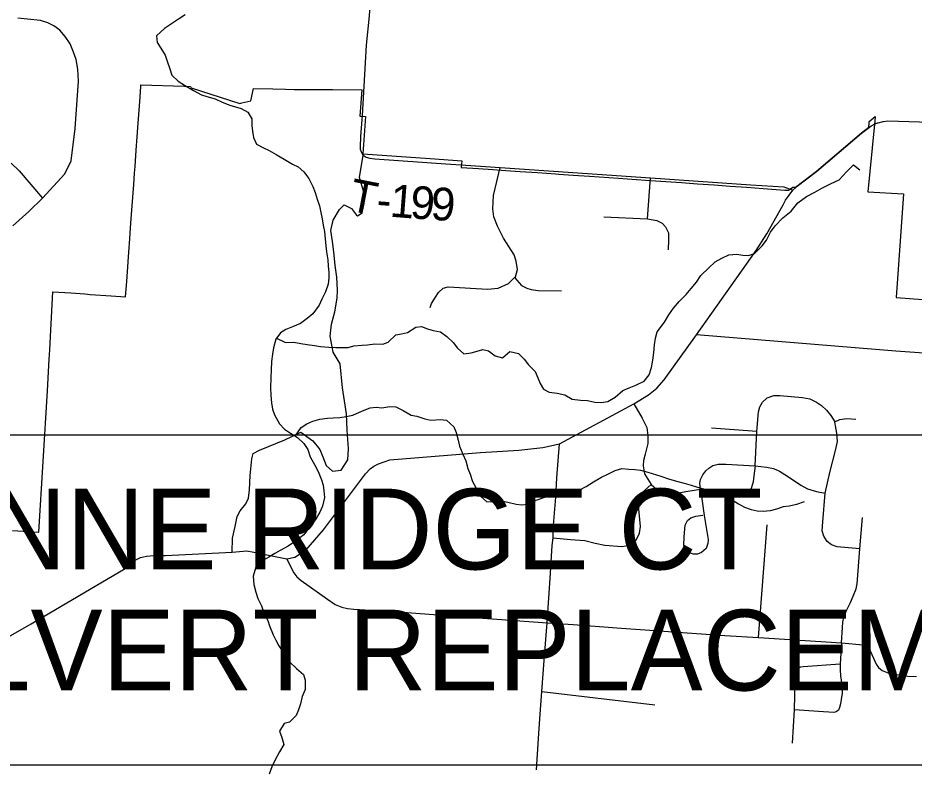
# Model space of a CAD drawing. Extents: x 208586767.6 to 208586821.4, y -134301046.9 to -134301022.9.
# Drawn here: x 208586781.515 to 208586783.069, y -134301028.957 to -134301027.656 of the extents above; entities that cross this region are included whole.
import ezdxf

# ---------------------------------------------------------------- set-up
doc = ezdxf.new("R2010")
doc.units = 0
for name, color, linetype in [('GM_X_City_Street', 7, 'Continuous'), ('GM_X_Corporation', 7, 'Continuous'), ('GM_X_County_Road', 7, 'Continuous'), ('GM_X_Minor_River', 7, 'Continuous'), ('GM_X_Township_Road', 7, 'Continuous'), ('GM_X_Township_Road_Text', 7, 'Continuous'), ('SH_Text', 7, 'Continuous')]:
    doc.layers.add(name, color=color, linetype=linetype)

msp = doc.modelspace()

# ---------------------------------------------------------------- linework, layer by layer
at = {"layer": 'GM_X_City_Street'}
for points in [[(208586781.5061, -134301028.0164), (208586781.534, -134301027.9913), (208586781.5576, -134301027.9684), (208586781.5965, -134301027.9262), (208586781.6071, -134301027.9038), (208586781.6143, -134301027.8478), (208586781.6198, -134301027.7655), (208586781.6188, -134301027.7446), (208586781.6157, -134301027.7277), (208586781.6115, -134301027.715), (208586781.6053, -134301027.7004), (208586781.5969, -134301027.6877), (208586781.5879, -134301027.6772), (208586781.5775, -134301027.6694), (208586781.5667, -134301027.6642), (208586781.5542, -134301027.66), (208586781.5313, -134301027.658), (208586781.5147, -134301027.6561)], [(208586781.5032, -134301027.9077), (208586781.5174, -134301027.9208), (208586781.5576, -134301027.9684)]]:
    msp.add_lwpolyline(points, dxfattribs=at)
at = {"layer": 'GM_X_Corporation'}
msp.add_lwpolyline([(208586781.5056, -134301028.5447), (208586781.5515, -134301028.5481), (208586781.5663, -134301028.3027), (208586781.5692, -134301028.2476), (208586781.5701, -134301028.2317), (208586781.5719, -134301028.1971), (208586781.5755, -134301028.1308), (208586781.5859, -134301028.1315), (208586781.6069, -134301028.1329), (208586781.6311, -134301028.1346), (208586781.6404, -134301028.1353), (208586781.6764, -134301028.1378), (208586781.7016, -134301028.1396), (208586781.7036, -134301028.1128), (208586781.7061, -134301028.0787), (208586781.7073, -134301028.0623), (208586781.7089, -134301028.0391), (208586781.7104, -134301028.0197), (208586781.7115, -134301028.0044), (208586781.7137, -134301027.9744), (208586781.7147, -134301027.9594), (208586781.7158, -134301027.9448), (208586781.7172, -134301027.925), (208586781.718, -134301027.9136), (208586781.7201, -134301027.8852), (208586781.7217, -134301027.862), (208586781.7234, -134301027.8385), (208586781.7245, -134301027.8234), (208586781.7256, -134301027.8083), (208586781.7267, -134301027.7931), (208586781.7281, -134301027.7741), (208586781.7282, -134301027.7719), (208586781.8036, -134301027.7741), (208586781.8141, -134301027.7744), (208586781.8155, -134301027.777), (208586781.8998, -134301027.804), (208586781.903, -134301027.8032), (208586781.9187, -134301027.7993), (208586781.9236, -134301027.7779), (208586781.957, -134301027.7788), (208586781.9791, -134301027.7794), (208586781.994, -134301027.7798), (208586782.0091, -134301027.7799), (208586782.0603, -134301027.7801), (208586782.111, -134301027.7804), (208586782.1079, -134301027.8262), (208586782.1173, -134301027.8266), (208586782.113, -134301027.8917), (208586782.1715, -134301027.8957), (208586782.2296, -134301027.8997), (208586782.2846, -134301027.9035), (208586782.2833, -134301027.915), (208586782.3136, -134301027.9171), (208586782.338, -134301027.9189), (208586782.3609, -134301027.9204), (208586782.3858, -134301027.9221), (208586782.4158, -134301027.9241), (208586782.4471, -134301027.9263), (208586782.4526, -134301027.9267), (208586782.4777, -134301027.9285), (208586782.5057, -134301027.9304), (208586782.556, -134301027.9339), (208586782.6029, -134301027.9371), (208586782.6204, -134301027.9382), (208586782.6653, -134301027.9414), (208586782.6933, -134301027.9434), (208586782.7218, -134301027.9455), (208586782.75, -134301027.9475), (208586782.7783, -134301027.9495), (208586782.8067, -134301027.9515), (208586782.8447, -134301027.9543), (208586782.851, -134301027.9546), (208586782.8582, -134301027.9493), (208586782.8631, -134301027.9491), (208586782.8992, -134301027.9216), (208586782.9774, -134301027.855), (208586782.99, -134301027.8452), (208586782.9906, -134301027.8378), (208586782.9908, -134301027.8352), (208586783.0011, -134301027.8267), (208586783.0004, -134301027.8347), (208586782.9994, -134301027.8458), (208586782.9883, -134301027.9572), (208586783.05, -134301027.9609), (208586783.0375, -134301028.1406), (208586783.1069, -134301028.1457)], dxfattribs=at)
at = {"layer": 'GM_X_County_Road'}
for points in [[(208586782.9968, -134301027.8415), (208586782.9984, -134301027.8406), (208586783.0054, -134301027.8379), (208586783.0063, -134301027.8377)], [(208586783.0063, -134301027.8377), (208586783.0147, -134301027.8352), (208586783.0158, -134301027.8351)], [(208586783.0158, -134301027.8351), (208586783.0232, -134301027.834), (208586783.1505, -134301027.8382), (208586783.1652, -134301027.8391)], [(208586782.8656, -134301027.9478), (208586782.8995, -134301027.9222), (208586782.9385, -134301027.8888), (208586782.9776, -134301027.8555), (208586782.9888, -134301027.847)], [(208586782.9888, -134301027.847), (208586782.9944, -134301027.8427), (208586782.9968, -134301027.8415)], [(208586782.4536, -134301028.3945), (208586782.5826, -134301028.3252), (208586782.6081, -134301028.3097), (208586782.6227, -134301028.2979), (208586782.6351, -134301028.2837), (208586782.6913, -134301028.2052), (208586782.7947, -134301028.0592), (208586782.8134, -134301028.0304), (208586782.8417, -134301027.98), (208586782.8454, -134301027.9721), (208586782.8518, -134301027.9629), (208586782.8586, -134301027.9547), (208586782.8633, -134301027.9496), (208586782.8656, -134301027.9478)], [(208586781.455, -134301028.7545), (208586781.5378, -134301028.7068), (208586781.7008, -134301028.6107), (208586781.7106, -134301028.6031), (208586781.7171, -134301028.597), (208586781.7277, -134301028.592), (208586781.738, -134301028.5897), (208586781.7502, -134301028.5882), (208586781.7711, -134301028.5881), (208586781.8864, -134301028.5823), (208586781.9119, -134301028.5801), (208586781.924, -134301028.5823), (208586781.9462, -134301028.5873), (208586781.9814, -134301028.5943), (208586781.995, -134301028.5911), (208586782.0144, -134301028.5784), (208586782.0448, -134301028.544), (208586782.1177, -134301028.4464), (208586782.1257, -134301028.438), (208586782.1317, -134301028.4334), (208586782.1401, -134301028.4292), (208586782.1595, -134301028.4222), (208586782.3168, -134301028.4094), (208586782.3833, -134301028.4055), (208586782.4248, -134301028.4009), (208586782.4536, -134301028.3945)]]:
    msp.add_lwpolyline(points, dxfattribs=at)
at = {"layer": 'GM_X_Minor_River'}
for points in [[(208586781.805, -134301027.6506), (208586781.7936, -134301027.6581), (208586781.7795, -134301027.6671), (208586781.7688, -134301027.6743), (208586781.7554, -134301027.6867), (208586781.7561, -134301027.6985), (208586781.7629, -134301027.7084), (208586781.77, -134301027.7202), (208586781.7738, -134301027.7309), (208586781.7782, -134301027.7442), (208586781.782, -134301027.7548), (208586781.7925, -134301027.7655), (208586781.8039, -134301027.7724), (208586781.8194, -134301027.7816), (208586781.833, -134301027.7893), (208586781.8424, -134301027.792), (208586781.8572, -134301027.7963), (208586781.8693, -134301027.8016), (208586781.8826, -134301027.807), (208586781.8921, -134301027.8097), (208586781.9019, -134301027.8128), (208586781.9136, -134301027.819), (208586781.9204, -134301027.8308), (208586781.9207, -134301027.8422), (208586781.9214, -134301027.852), (208586781.9236, -134301027.8634), (208586781.9288, -134301027.8745), (208586781.9406, -134301027.881), (208586781.9504, -134301027.8856), (208586781.9625, -134301027.8929), (208586781.9765, -134301027.9006), (208586781.9909, -134301027.9094), (208586782.0007, -134301027.914), (208586782.0109, -134301027.9228), (208586782.0192, -134301027.9342), (208586782.0263, -134301027.9479), (208586782.03, -134301027.9586), (208586782.0337, -134301027.9704), (208586782.0379, -134301027.9818), (208586782.0401, -134301027.9935), (208586782.0426, -134301028.0042), (208586782.0441, -134301028.0152), (208586782.0463, -134301028.0262), (208586782.0477, -134301028.0391), (208586782.0488, -134301028.0513), (208586782.0499, -134301028.0615), (208586782.0521, -134301028.0752), (208586782.0531, -134301028.0862), (208586782.0538, -134301028.0969), (208586782.0538, -134301028.1067), (208586782.0526, -134301028.1173), (208586782.0483, -134301028.1306), (208586782.0421, -134301028.1438), (208586782.0375, -134301028.1541), (208586782.0261, -134301028.1688), (208586782.0165, -134301028.1771), (208586782.0051, -134301028.1861), (208586781.991, -134301028.1917), (208586781.9796, -134301028.1962), (208586781.9701, -134301028.2019), (208586781.962, -134301028.2132), (208586781.9581, -134301028.228), (208586781.9565, -134301028.2393), (208586781.9546, -134301028.2519), (208586781.9541, -134301028.2663)], [(208586781.9633, -134301028.2113), (208586781.9787, -134301028.2186), (208586781.9931, -134301028.2183), (208586782.0056, -134301028.2207), (208586782.0162, -134301028.2222), (208586782.0291, -134301028.2238), (208586782.0397, -134301028.2258), (208586782.0542, -134301028.227), (208586782.0659, -134301028.2275), (208586782.0765, -134301028.2275), (208586782.0875, -134301028.2272), (208586782.0974, -134301028.2246), (208586782.1115, -134301028.2232), (208586782.121, -134301028.2229), (208586782.1335, -134301028.221), (208586782.1476, -134301028.2219), (208586782.1571, -134301028.2181), (208586782.1704, -134301028.2053), (208586782.1799, -134301028.2035), (208586782.1906, -134301028.2016), (208586782.205, -134301028.1922), (208586782.2145, -134301028.1912), (208586782.2251, -134301028.195), (208586782.2346, -134301028.1977), (208586782.2475, -134301028.2005), (208586782.2588, -134301028.2085), (208586782.2698, -134301028.2188), (208586782.2769, -134301028.2287), (208586782.2879, -134301028.2383), (208586782.3008, -134301028.2365), (208586782.3114, -134301028.2339), (208586782.3209, -134301028.2309), (208586782.3308, -134301028.2332), (208586782.3425, -134301028.242), (208586782.355, -134301028.2455), (208586782.3676, -134301028.2346), (208586782.3828, -134301028.2377), (208586782.3926, -134301028.2476), (208586782.4001, -134301028.2575), (208586782.4118, -134301028.269), (208586782.4163, -134301028.28), (208586782.4204, -134301028.2899), (208586782.426, -134301028.2998), (208586782.4359, -134301028.3048), (208586782.4499, -134301028.3068), (208586782.4632, -134301028.3095), (208586782.4756, -134301028.3172), (208586782.49, -134301028.3188), (208586782.5026, -134301028.3196), (208586782.5151, -134301028.3224), (208586782.5261, -134301028.3228), (208586782.5375, -134301028.321), (208586782.5504, -134301028.3138), (208586782.5638, -134301028.3018), (208586782.5748, -134301028.2977), (208586782.5862, -134301028.2928), (208586782.6007, -134301028.2857), (208586782.6091, -134301028.2747), (208586782.6134, -134301028.2622), (208586782.6154, -134301028.2497), (208586782.6173, -134301028.2364), (208586782.6186, -134301028.2228), (208586782.6201, -134301028.2114), (208586782.6232, -134301028.2004), (208586782.6359, -134301028.1834), (208586782.6436, -134301028.1709), (208586782.6516, -134301028.1592), (208586782.6612, -134301028.1475), (208586782.6734, -134301028.1354), (208586782.6822, -134301028.1249), (208586782.6914, -134301028.1139), (208586782.699, -134301028.1026), (208586782.7128, -134301028.089), (208586782.7238, -134301028.0788), (208586782.7353, -134301028.0724), (208586782.7474, -134301028.0668), (208586782.7615, -134301028.0658), (208586782.7714, -134301028.067), (208586782.7816, -134301028.0678), (208586782.7919, -134301028.0641), (208586782.8052, -134301028.0508), (208586782.8129, -134301028.041), (208586782.8198, -134301028.0274), (208586782.8275, -134301028.0164), (208586782.8412, -134301028.0025), (208586782.8553, -134301027.9912), (208586782.8668, -134301027.9765), (208586782.8821, -134301027.9655), (208586782.8965, -134301027.9577), (208586782.9087, -134301027.9513), (208586782.9251, -134301027.943), (208586782.9388, -134301027.9363), (208586782.9514, -134301027.9227), (208586782.9636, -134301027.9106), (208586782.9746, -134301027.919)], [(208586781.9541, -134301028.2663), (208586781.9532, -134301028.2799), (208586781.9528, -134301028.2974), (208586781.9534, -134301028.3103), (208586781.9545, -134301028.3232), (208586781.9563, -134301028.3346), (208586781.9597, -134301028.3441), (208586781.9683, -134301028.3597), (208586781.977, -134301028.3692), (208586781.9876, -134301028.3761), (208586781.9997, -134301028.3834), (208586782.0106, -134301028.3941), (208586782.0177, -134301028.4044), (208586782.0215, -134301028.4173), (208586782.0297, -134301028.4314), (208586782.0357, -134301028.4425), (208586782.0413, -134301028.4569), (208586782.0439, -134301028.4664), (208586782.0454, -134301028.4759), (208586782.0464, -134301028.4877), (208586782.0429, -134301028.5025), (208586782.0383, -134301028.5131), (208586782.031, -134301028.5259), (208586782.0196, -134301028.5395), (208586782.0107, -134301028.5524), (208586781.9966, -134301028.5629), (208586781.9833, -134301028.5719), (208586781.9696, -134301028.5798), (208586781.9601, -134301028.5847), (208586781.9502, -134301028.5911), (208586781.938, -134301028.5982), (208586781.9277, -134301028.6084), (208586781.923, -134301028.6239), (208586781.9237, -134301028.6384), (208586781.9274, -134301028.6521), (208586781.9307, -134301028.6627), (208586781.9371, -134301028.6756), (208586781.942, -134301028.6889), (208586781.948, -134301028.7011), (208586781.9509, -134301028.7106), (208586781.9573, -134301028.7258), (208586781.9622, -134301028.7354), (208586781.9674, -134301028.7449), (208586781.9764, -134301028.759), (208586781.9858, -134301028.7727), (208586781.9979, -134301028.7841), (208586782.01, -134301028.7945), (208586782.013, -134301028.8043), (208586782.0129, -134301028.8207), (208586782.0075, -134301028.8332), (208586782.0047, -134301028.8457), (208586782.0016, -134301028.8563), (208586781.9974, -134301028.8661), (208586781.9859, -134301028.8774), (208586781.9764, -134301028.88), (208586781.9684, -134301028.8933), (208586781.9725, -134301028.9039), (208586781.9762, -134301028.9161), (208586781.9682, -134301028.9289), (208586781.9612, -134301028.9429), (208586781.9551, -134301028.9547), (208586781.9508, -134301028.9675)], [(208586781.9958, -134301028.3811), (208586782.0062, -134301028.366), (208586782.0161, -134301028.36), (208586782.0264, -134301028.3555), (208586782.0382, -134301028.3518), (208586782.0515, -134301028.3503), (208586782.0617, -134301028.3496), (208586782.0731, -134301028.3489), (208586782.0841, -134301028.3471), (208586782.0955, -134301028.3449), (208586782.1123, -134301028.3374), (208586782.1256, -134301028.3322), (208586782.1359, -134301028.3311), (208586782.1461, -134301028.3319), (208586782.1598, -134301028.3297), (208586782.1704, -134301028.3302), (208586782.1829, -134301028.3367), (208586782.1969, -134301028.3451), (208586782.2064, -134301028.3463), (208586782.2204, -134301028.3513), (208586782.231, -134301028.3537), (208586782.2477, -134301028.3526), (208586782.2579, -134301028.3535), (208586782.2704, -134301028.3649), (208586782.2749, -134301028.3748), (208586782.2782, -134301028.3881), (208586782.2804, -134301028.3988), (208586782.286, -134301028.4124), (208586782.2913, -134301028.4239), (208586782.295, -134301028.4372), (208586782.2987, -134301028.4471), (208586782.3032, -134301028.46), (208586782.3088, -134301028.4706), (208586782.3171, -134301028.4851), (208586782.3276, -134301028.495), (208586782.3402, -134301028.4947), (208586782.3535, -134301028.4937), (208586782.3641, -134301028.4956), (208586782.3785, -134301028.4991), (208586782.3883, -134301028.5003), (208586782.3982, -134301028.4993), (208586782.4134, -134301028.4921), (208586782.4283, -134301028.4873), (208586782.4389, -134301028.4858), (208586782.4503, -134301028.484), (208586782.4636, -134301028.4803), (208586782.4758, -134301028.4766), (208586782.4891, -134301028.4744), (208586782.5001, -134301028.4687), (208586782.5127, -134301028.4605), (208586782.5256, -134301028.453), (208586782.5397, -134301028.4458), (208586782.5504, -134301028.4406), (208586782.5618, -134301028.4376), (208586782.5743, -134301028.4384), (208586782.5842, -134301028.4389), (208586782.5944, -134301028.4405), (208586782.6069, -134301028.4436), (208586782.6297, -134301028.4505), (208586782.6429, -134301028.4552), (208586782.6569, -134301028.4594), (208586782.6702, -134301028.4626), (208586782.6823, -134301028.466), (208586782.6929, -134301028.4695), (208586782.7035, -134301028.4726), (208586782.7149, -134301028.4765), (208586782.7262, -134301028.4807), (208586782.7403, -134301028.4854), (208586782.7505, -134301028.49), (208586782.7641, -134301028.4984), (208586782.7747, -134301028.5045), (208586782.786, -134301028.5084), (208586782.7963, -134301028.5111), (208586782.8069, -134301028.5116), (208586782.8198, -134301028.5105), (208586782.8305, -134301028.5075), (208586782.8422, -134301028.5034), (208586782.8521, -134301028.5023), (208586782.8654, -134301028.499), (208586782.8787, -134301028.4945)]]:
    msp.add_lwpolyline(points, dxfattribs=at)
at = {"layer": 'GM_X_Township_Road'}
for p, q in [((208586782.6067, -134301028.0045), (208586782.6114, -134301027.9331)), ((208586782.7962, -134301028.3731), (208586782.7174, -134301028.3673)), ((208586782.7991, -134301028.7306), (208586782.8139, -134301028.5349)), ((208586782.9743, -134301028.5766), (208586782.979, -134301028.5223)), ((208586782.4234, -134301028.824), (208586782.619, -134301028.8472)), ((208586782.8575, -134301028.9136), (208586782.8615, -134301028.856))]:
    msp.add_line(p, q, dxfattribs=at)
for points in [[(208586782.1124, -134301027.8249), (208586782.1194, -134301027.7029), (208586782.1245, -134301027.6519), (208586782.1281, -134301027.6007), (208586782.1288, -134301027.5917), (208586782.1274, -134301027.5863), (208586782.1245, -134301027.5826), (208586782.1201, -134301027.5803), (208586782.1149, -134301027.5792), (208586782.1009, -134301027.5787), (208586782.0865, -134301027.5785), (208586782.0807, -134301027.5776)], [(208586782.1135, -134301027.894), (208586782.1107, -134301027.8888), (208586782.1091, -134301027.8837), (208586782.1087, -134301027.8793), (208586782.1097, -134301027.8614), (208586782.112, -134301027.8318), (208586782.1124, -134301027.8249)], [(208586781.8864, -134301028.5823), (208586781.8869, -134301028.5584), (208586781.8914, -134301028.5379), (208586781.8952, -134301028.5208), (208586781.9002, -134301028.5108), (208586781.9102, -134301028.4986), (208586781.9146, -134301028.4886), (208586781.9163, -134301028.4742), (208586781.9174, -134301028.4493), (208586781.9202, -134301028.4205), (208586781.9229, -134301028.4111), (208586781.934, -134301028.4055), (208586781.9778, -134301028.3878), (208586782.0053, -134301028.3741), (208586782.0263, -134301028.3892), (208586782.0381, -134301028.4044), (208586782.0434, -134301028.4169), (208586782.0496, -134301028.4321), (208586782.0606, -134301028.442), (208586782.0754, -134301028.44), (208586782.0868, -134301028.4225), (208586782.0879, -134301028.4031), (208586782.0859, -134301028.3709), (208586782.0847, -134301028.3424), (208586782.0774, -134301028.2976), (208586782.0739, -134301028.2558), (208586782.0616, -134301028.2357), (208586782.0563, -134301028.2076), (208586782.0585, -134301028.187), (208586782.0645, -134301028.1654), (208586782.0687, -134301028.1418), (208586782.069, -134301028.1278), (208586782.0678, -134301028.1057), (208586782.0651, -134301028.0852), (208586782.0628, -134301028.0617), (208586782.0604, -134301028.0438), (208586782.0577, -134301028.0245), (208586782.0615, -134301028.0066), (208586782.0725, -134301027.9883), (208586782.0808, -134301027.98), (208586782.093, -134301027.9864), (208586782.1022, -134301027.9981), (208586782.1037, -134301027.9989), (208586782.112, -134301027.9936), (208586782.1154, -134301027.9776), (208586782.1146, -134301027.9578), (208586782.107, -134301027.9324), (208586782.1135, -134301027.894)], [(208586782.1135, -134301027.894), (208586782.1187, -134301027.8973), (208586782.1248, -134301027.8992), (208586782.134, -134301027.9003), (208586782.2567, -134301027.9088), (208586782.2915, -134301027.911)], [(208586782.2296, -134301028.1582), (208586782.2319, -134301028.1509), (208586782.2387, -134301028.1399), (208586782.244, -134301028.1319), (208586782.252, -134301028.1243), (208586782.2611, -134301028.1224), (208586782.3292, -134301028.126), (208586782.3475, -134301028.1248), (208586782.3657, -134301028.1164), (208586782.3758, -134301028.1063), (208586782.3775, -134301028.1046), (208586782.3809, -134301028.0921), (208586782.3785, -134301028.0776), (208586782.3755, -134301028.0666), (208586782.3568, -134301028.0378), (208586782.3464, -134301028.0169), (208586782.3399, -134301028.0006), (208586782.338, -134301027.9869), (208586782.3395, -134301027.9638), (208586782.3512, -134301027.9149)], [(208586782.2915, -134301027.911), (208586782.3512, -134301027.9149), (208586782.6114, -134301027.9331), (208586782.7856, -134301027.9455), (208586782.843, -134301027.949), (208586782.8586, -134301027.9547)], [(208586782.5307, -134301028.0006), (208586782.6067, -134301028.0045), (208586782.6228, -134301028.0073), (208586782.6319, -134301028.0115), (208586782.6376, -134301028.0182), (208586782.6427, -134301028.0283), (208586782.6427, -134301028.0403), (208586782.6422, -134301028.0579)], [(208586782.3758, -134301028.1063), (208586782.3882, -134301028.1198), (208586782.3973, -134301028.1243), (208586782.4045, -134301028.127), (208586782.4167, -134301028.1285), (208586782.4574, -134301028.1291)], [(208586783.1307, -134301028.8049), (208586783.1355, -134301028.7186), (208586783.141, -134301028.6526), (208586783.1529, -134301028.4806), (208586783.1566, -134301028.423), (208586783.1647, -134301028.3003), (208586783.1679, -134301028.2561), (208586783.1671, -134301028.2499), (208586783.1641, -134301028.2444), (208586783.1587, -134301028.2422), (208586783.0371, -134301028.2339), (208586782.6913, -134301028.2052)], [(208586782.7933, -134301028.4329), (208586782.7962, -134301028.3731), (208586782.799, -134301028.3389), (208586782.8009, -134301028.3301), (208586782.8056, -134301028.3224), (208586782.8141, -134301028.315), (208586782.8254, -134301028.3108), (208586782.8359, -134301028.3108), (208586782.8753, -134301028.3141), (208586782.8877, -134301028.3166), (208586782.8993, -134301028.3221), (208586782.9079, -134301028.3279), (208586782.917, -134301028.3362), (208586782.9244, -134301028.3456), (208586782.931, -134301028.3563)], [(208586782.5826, -134301028.3252), (208586782.5972, -134301028.3499), (208586782.6054, -134301028.3663), (208586782.6072, -134301028.38), (208586782.6068, -134301028.3941), (208586782.6022, -134301028.4123), (208586782.5995, -134301028.4233), (208586782.599, -134301028.4329), (208586782.6013, -134301028.4466), (208586782.6127, -134301028.4653), (208586782.6223, -134301028.4735), (208586782.6314, -134301028.4785), (208586782.6401, -134301028.4808), (208586782.6538, -134301028.4808), (208586782.6766, -134301028.4767), (208586782.6984, -134301028.4735)], [(208586782.9743, -134301028.5766), (208586782.9352, -134301028.573), (208586782.9252, -134301028.5697), (208586782.9181, -134301028.5639), (208586782.9123, -134301028.5548), (208586782.9095, -134301028.5457), (208586782.9101, -134301028.5297), (208586782.9145, -134301028.4801), (208586782.9225, -134301028.4445), (208586782.9321, -134301028.4062), (208586782.9357, -134301028.3905), (208586782.9346, -134301028.3759), (208586782.9321, -134301028.3632), (208586782.931, -134301028.3563)], [(208586782.931, -134301028.3563), (208586782.9398, -134301028.3522), (208586782.9517, -134301028.3505), (208586782.9675, -134301028.3518)], [(208586782.4141, -134301028.9603), (208586782.4175, -134301028.9056), (208586782.4199, -134301028.8717), (208586782.4234, -134301028.824), (208586782.4275, -134301028.7703), (208586782.4323, -134301028.7051), (208586782.4381, -134301028.6189), (208586782.4411, -134301028.5709), (208586782.4429, -134301028.5575), (208586782.4436, -134301028.5354), (208586782.4475, -134301028.487), (208586782.4495, -134301028.4534), (208586782.4536, -134301028.3945)], [(208586782.6984, -134301028.4735), (208586782.6973, -134301028.463), (208586782.6984, -134301028.4564), (208586782.7021, -134301028.4482), (208586782.7076, -134301028.4415), (208586782.7126, -134301028.4368), (208586782.7199, -134301028.4324), (208586782.7292, -134301028.4301), (208586782.7422, -134301028.4301), (208586782.7933, -134301028.4329), (208586782.8128, -134301028.4351), (208586782.8249, -134301028.4373), (208586782.8354, -134301028.4418), (208586782.8494, -134301028.4506), (208586782.8723, -134301028.4663), (208586782.8836, -134301028.4724), (208586782.8996, -134301028.4773), (208586782.9145, -134301028.4801)], [(208586782.7933, -134301028.4329), (208586782.791, -134301028.4503), (208586782.7896, -134301028.4605), (208586782.7863, -134301028.4721), (208586782.7794, -134301028.4842)], [(208586782.4429, -134301028.5575), (208586782.4727, -134301028.5606), (208586782.4978, -134301028.562), (208586782.5156, -134301028.567), (208586782.5324, -134301028.5702), (208586782.5621, -134301028.5729), (208586782.5744, -134301028.5702), (208586782.5872, -134301028.5606), (208586782.5926, -134301028.5496), (208586782.594, -134301028.5378), (208586782.5908, -134301028.5017), (208586782.5913, -134301028.4894), (208586782.5958, -134301028.4799), (208586782.6127, -134301028.4653)], [(208586782.6984, -134301028.4735), (208586782.7048, -134301028.5188), (208586782.7114, -134301028.5606), (208586782.7108, -134301028.5675), (208586782.708, -134301028.5763), (208586782.7003, -134301028.5829), (208586782.6931, -134301028.5859), (208586782.6862, -134301028.5862), (208586782.6777, -134301028.5829), (208586782.6722, -134301028.5774), (208586782.6694, -134301028.5702), (208586782.6702, -134301028.5562), (208586782.6719, -134301028.5358), (208586782.6755, -134301028.5275), (208586782.6815, -134301028.5231), (208586782.6904, -134301028.5198), (208586782.7023, -134301028.5182)], [(208586782.943, -134301028.7401), (208586782.9446, -134301028.7135), (208586782.9453, -134301028.704), (208586782.9469, -134301028.696), (208586782.9509, -134301028.6846), (208586782.9583, -134301028.6698), (208586782.963, -134301028.6587), (208586782.9682, -134301028.646), (208586782.9699, -134301028.6372), (208586782.9743, -134301028.5766)], [(208586781.9814, -134301028.5943), (208586781.9879, -134301028.6087), (208586781.9932, -134301028.6185), (208586781.9987, -134301028.6253), (208586782.006, -134301028.6316), (208586782.0519, -134301028.6642), (208586782.0651, -134301028.6731), (208586782.0764, -134301028.6781), (208586782.0866, -134301028.6805), (208586782.0971, -134301028.6816), (208586782.174, -134301028.6863), (208586782.289, -134301028.6948), (208586782.3771, -134301028.7009), (208586782.4323, -134301028.7051), (208586782.4423, -134301028.7058)], [(208586782.4423, -134301028.7058), (208586782.4773, -134301028.7082), (208586782.5534, -134301028.7138), (208586782.7403, -134301028.7269), (208586782.7991, -134301028.7306), (208586782.943, -134301028.7401), (208586782.9803, -134301028.7434), (208586782.9842, -134301028.7448), (208586782.9877, -134301028.7471), (208586782.9902, -134301028.7503), (208586782.9928, -134301028.755), (208586783.0027, -134301028.777), (208586783.007, -134301028.7827), (208586783.0132, -134301028.7877), (208586783.0217, -134301028.7912), (208586783.0344, -134301028.7943), (208586783.0579, -134301028.7977), (208586783.0726, -134301028.7983)], [(208586782.943, -134301028.7401), (208586782.9405, -134301028.7763), (208586782.9404, -134301028.7788), (208586782.9403, -134301028.7863), (208586782.9411, -134301028.7976), (208586782.9421, -134301028.8038), (208586782.9429, -134301028.8092), (208586782.9436, -134301028.8184), (208586782.9436, -134301028.8271), (208586782.9424, -134301028.8382), (208586782.941, -134301028.8458), (208586782.9393, -134301028.852), (208586782.9377, -134301028.8568), (208586782.9336, -134301028.8595), (208586782.9295, -134301028.8606), (208586782.9026, -134301028.8587), (208586782.8615, -134301028.856), (208586782.8624, -134301028.8067), (208586782.8634, -134301028.7921), (208586782.865, -134301028.7868), (208586782.8681, -134301028.7832), (208586782.872, -134301028.7812), (208586782.8765, -134301028.7806), (208586782.9405, -134301028.7763)]]:
    msp.add_lwpolyline(points, dxfattribs=at)
at = {"layer": 'SH_Text'}
msp.add_lwpolyline([(208586781.104, -134301028.379), (208586783.373, -134301028.379), (208586783.373, -134301028.9519), (208586781.104, -134301028.9519)], close=True, dxfattribs=at)

# ---------------------------------------------------------------- texts
at = {"layer": 'GM_X_Township_Road_Text'}
for s, rotation, p in [('T', 348.9868, (208586782.0863, -134301027.9896)), ('1', 355.5722, (208586782.1585, -134301028.0004)), ('9', 355.7213, (208586782.1936, -134301028.0031)), ('9', 356.6817, (208586782.2295, -134301028.0058)), ('-', 355.8112, (208586782.1353, -134301027.9987))]:
    msp.add_text(s, height=0.0568, rotation=rotation, dxfattribs=at).set_placement(p)
at = {"layer": 'SH_Text'}
for s, p in [('WYNNE RIDGE CT          ', (208586781.1624, -134301028.6124)), ('CULVERT REPLACEMENT', (208586781.1624, -134301028.8224))]:
    msp.add_text(s, height=0.14, dxfattribs=at).set_placement(p)

doc.saveas('drawing.dxf')
